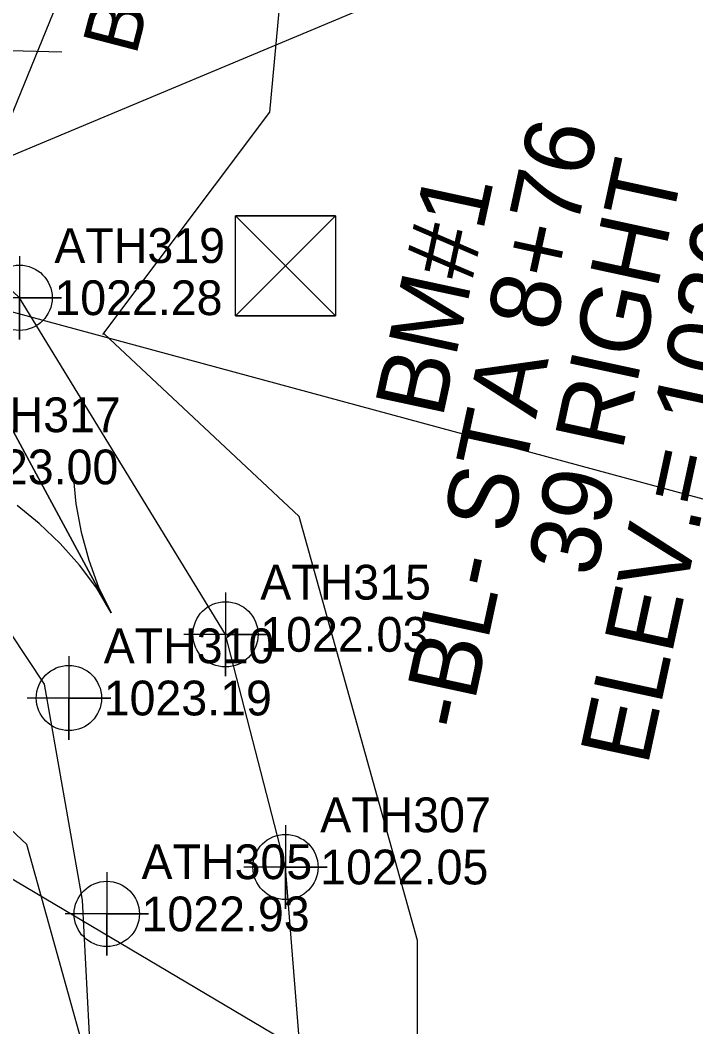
# Model space of a CAD drawing. Extents: x 1212084 to 1214478, y 765637 to 767408.
# Drawn here: x 1213368.1 to 1213416.6, y 766428.2 to 766500.6 of the extents above; entities that cross this region are included whole.
import ezdxf

# ---------------------------------------------------------------- set-up
doc = ezdxf.new("R2010")
doc.units = 0
for name, color, linetype in [('CTL Sheet Text', 7, 'Continuous'), ('CTL Vertical Benchmark CELL', 7, 'Continuous'), ('Exist DTM Drainline Cogo Elevation', 7, 'Continuous'), ('Exist DTM Drainline Cogo Number', 7, 'Continuous'), ('Exist DTM Drainline Cogo Point CELL', 7, 'Continuous'), ('Exist Hydro Jurisdictional Stream or Body of Water', 7, 'Continuous'), ('Exist Hydro River Flow Arrow CELL', 7, 'Continuous'), ('Exist Property Line', 7, 'Continuous'), ('Exist Roads EOP', 7, 'Continuous'), ('Exist Structure Major Deck Tunnel Box Culvert Leader', 7, 'Continuous'), ('Exist Structure Major Deck Tunnel Box Culvert Text', 7, 'Continuous'), ('Exist Utilities Other Located Object Text', 7, 'Continuous'), ('Exist Utilities Water UG Line SUE LOS B', 7, 'Continuous'), ('Exist Vegetation Woods Line', 7, 'Continuous')]:
    doc.layers.add(name, color=color, linetype=linetype)

msp = doc.modelspace()

# ---------------------------------------------------------------- linework, layer by layer
at = {"layer": 'CTL Vertical Benchmark CELL'}
msp.add_line((1213387.143, 766482.938), (1213387.143, 766482.938), dxfattribs=at)
msp.add_lwpolyline([(1213383.543, 766486.525), (1213390.731, 766486.525), (1213390.731, 766479.338), (1213383.543, 766479.338)], close=True, dxfattribs=at)
for points in [[(1213390.731, 766486.525), (1213383.543, 766479.338), (1213387.137, 766482.932), (1213390.731, 766479.338), (1213383.543, 766486.525)], [(1213387.137, 766482.932), (1213390.731, 766486.525), (1213383.543, 766486.525), (1213387.137, 766482.932)], [(1213387.137, 766482.932), (1213383.543, 766479.338), (1213390.731, 766479.338), (1213387.137, 766482.932)]]:
    msp.add_lwpolyline(points, dxfattribs=at)
at = {"layer": 'Exist DTM Drainline Cogo Point CELL'}
for points in [[(1213368.024, 766483.627), (1213368.024, 766477.627), (1213368.024, 766480.627), (1213371.024, 766480.627), (1213365.024, 766480.627)], [(1213382.822, 766459.43), (1213382.822, 766453.43), (1213382.822, 766456.43), (1213385.822, 766456.43), (1213379.822, 766456.43)], [(1213371.57, 766454.854), (1213371.57, 766448.854), (1213371.57, 766451.854), (1213374.57, 766451.854), (1213368.57, 766451.854)], [(1213387.132, 766442.706), (1213387.132, 766436.706), (1213387.132, 766439.706), (1213390.132, 766439.706), (1213384.132, 766439.706)], [(1213374.288, 766439.335), (1213374.288, 766433.335), (1213374.288, 766436.335), (1213377.288, 766436.335), (1213371.288, 766436.335)]]:
    msp.add_lwpolyline(points, dxfattribs=at)
for centre in [(1213368.024, 766480.627), (1213382.822, 766456.43), (1213371.57, 766451.854), (1213387.132, 766439.706), (1213374.288, 766436.335)]:
    msp.add_circle(centre, 2.344, dxfattribs=at)
at = {"layer": 'Exist Hydro Jurisdictional Stream or Body of Water'}
for points in [[(1213458.541, 766244.269), (1213458.541, 766244.269), (1213446.982, 766261.332), (1213440.132, 766307.328), (1213429.645, 766367.831), (1213400.182, 766384.285), (1213389.875, 766405.51), (1213387.132, 766439.706), (1213382.822, 766456.43), (1213368.024, 766480.627), (1213349.519, 766498.124), (1213343.218, 766500.032)], [(1213526.436, 766209.954), (1213516.378, 766233.157), (1213480.9, 766229.639), (1213448.854, 766229.857), (1213432.873, 766257.536), (1213423.253, 766306.329), (1213418.782, 766357.325), (1213383.349, 766377.624), (1213374.57, 766398.221), (1213372.54, 766437.336), (1213369.822, 766452.855), (1213358.786, 766469.465), (1213340.365, 766470.464), (1213333.312, 766472.183)]]:
    msp.add_lwpolyline(points, dxfattribs=at)
at = {"layer": 'Exist Hydro River Flow Arrow CELL'}
msp.add_line((1213369.855, 766466.77), (1213369.855, 766466.77), dxfattribs=at)
msp.add_lwpolyline([(1213371.867, 766467.859), (1213372.073, 766465.824), (1213372.452, 766463.784), (1213373.004, 766461.766), (1213373.705, 766459.814), (1213374.615, 766457.976), (1213365.096, 766475.565), (1213374.615, 766457.976), (1213373.573, 766459.743), (1213372.323, 766461.397), (1213370.935, 766462.963), (1213369.434, 766464.397), (1213367.844, 766465.682)], dxfattribs=at)
at = {"layer": 'Exist Property Line'}
msp.add_line((1213348.537, 766484.754), (1213513.863, 766439.963), dxfattribs=at)
at = {"layer": 'Exist Roads EOP'}
msp.add_spline([(1213331.542, 766460.381), (1213328.202, 766439.131), (1213326.882, 766418.055), (1213328.894, 766392.003), (1213339.56, 766359.268), (1213347.201, 766343.262), (1213357.639, 766324.019), (1213372.578, 766298.933)], degree=3, dxfattribs=at)
at = {"layer": 'Exist Structure Major Deck Tunnel Box Culvert Leader'}
msp.add_line((1213338.336, 766499.181), (1213371.06, 766498.304), dxfattribs=at)
at = {"layer": 'Exist Utilities Other Located Object Text'}
for p, q in [((1213357.472, 766486.673), (1213475.622, 766536.167)), ((1213325.77, 766463.572), (1213448.139, 766391.086))]:
    msp.add_line(p, q, dxfattribs=at)
at = {"layer": 'Exist Utilities Water UG Line SUE LOS B'}
msp.add_lwpolyline([(1213312.252, 766356.682), (1213342.315, 766369.143), (1213353.998, 766372.079), (1213350.927, 766383.418), (1213347.777, 766424.606), (1213351.576, 766454.854), (1213376.387, 766515.679), (1213382.751, 766545.226), (1213385.129, 766575.512), (1213387.127, 766612.966), (1213395.365, 766676.737), (1213413.112, 766741.363), (1213427.394, 766793.323), (1213430.959, 766811.701)], dxfattribs=at)
at = {"layer": 'Exist Vegetation Woods Line'}
for points in [[(1213374.017, 766477.977), (1213386.003, 766493.965), (1213388.001, 766515.449), (1213408.977, 766517.947), (1213441.439, 766491.966), (1213442.438, 766435.008), (1213441.439, 766410.526), (1213451.927, 766416.022)], [(1213452.553, 766272.553), (1213440.567, 766351.995), (1213434.074, 766378.975), (1213409.603, 766394.963), (1213396.618, 766410.451), (1213396.618, 766434.434), (1213388.128, 766464.911), (1213374.113, 766478.027)], [(1213432.962, 766248.974), (1213420.975, 766328.415), (1213414.483, 766355.395), (1213390.011, 766371.384), (1213377.026, 766386.872), (1213377.026, 766410.854), (1213368.536, 766441.332), (1213354.521, 766454.447)]]:
    msp.add_lwpolyline(points, dxfattribs=at)

# ---------------------------------------------------------------- texts
at = {"layer": 'CTL Sheet Text'}
for s, p in [("ELEV.= 1026.96'", (1213413.156, 766446.893)), ('-BL- STA 8+76', (1213400.26, 766449.357)), ('39 RIGHT', (1213409.369, 766460.439)), ('BM#1', (1213398.411, 766471.87))]:
    msp.add_text(s, height=5, rotation=77.8065, dxfattribs=at).set_placement(p)
at = {"layer": 'Exist DTM Drainline Cogo Elevation'}
for s, p in [('1022.28', (1213370.524, 766479.377)), ('1023.00', (1213363.034, 766467.214)), ('1022.03', (1213385.322, 766455.18)), ('1023.19', (1213374.07, 766450.604)), ('1022.05', (1213389.632, 766438.456)), ('1022.93', (1213376.788, 766435.085))]:
    msp.add_text(s, height=2.5, dxfattribs=at).set_placement(p)
at = {"layer": 'Exist DTM Drainline Cogo Number'}
for s, p in [('ATH319', (1213370.524, 766483.127)), ('ATH317', (1213363.034, 766470.964)), ('ATH315', (1213385.322, 766458.93)), ('ATH310', (1213374.07, 766454.354)), ('ATH307', (1213389.632, 766442.206)), ('ATH305', (1213376.788, 766438.835))]:
    msp.add_text(s, height=2.5, dxfattribs=at).set_placement(p)
at = {"layer": 'Exist Structure Major Deck Tunnel Box Culvert Text'}
msp.add_text('BRIDGE #110145', height=4, rotation=75.42683, dxfattribs=at).set_placement((1213376.386, 766497.968))

doc.saveas('drawing.dxf')
